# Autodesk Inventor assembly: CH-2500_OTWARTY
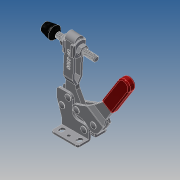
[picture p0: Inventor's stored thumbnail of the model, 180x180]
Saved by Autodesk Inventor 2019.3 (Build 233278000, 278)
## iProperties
Company: Î¢ÈíÖÐ¹ú
Created: 2012-09
Part Number: CH-2500_OTWARTY
Material: Ogólny
Description: STEP AP203
Document SubType Name: Assembly
Designer: CADENGINEERING4
Sending System: SolidWorks 2010
Preprocessor: SwSTEP 2.0
Title: CH-2500.STEP
Author: Î¢ÈíÓÃ»§
Revision Number: ÈÎºÎ
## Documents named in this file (12)
- E:\STRONA\Horizontal toggle clamp\CH-2500\CH-2500_OTWARTY.iam
- E:\STRONA\Horizontal toggle clamp\CH-2500\CH-36092M-06___.ipt
- E:\STRONA\Horizontal toggle clamp\CH-2500\CH-2500-06___.ipt
- E:\STRONA\Horizontal toggle clamp\CH-2500\CH-2500-03___.ipt
- E:\STRONA\Horizontal toggle clamp\CH-2500\CH-FC-56300___.ipt
- E:\STRONA\Horizontal toggle clamp\CH-2500\CH-2500-01___.ipt
- E:\STRONA\Horizontal toggle clamp\CH-2500\CH-11401-05___.ipt
- E:\STRONA\Horizontal toggle clamp\CH-2500\CH-2500-02___.ipt
- E:\STRONA\Horizontal toggle clamp\CH-2500\FW516___.ipt
- E:\STRONA\Horizontal toggle clamp\CH-2500\CH-2500-04___.ipt
- E:\STRONA\Horizontal toggle clamp\CH-2500\CH-FC-56300-02___.ipt
- E:\STRONA\Horizontal toggle clamp\CH-2500\CH-2500-05___.ipt
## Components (20 placed, 20 different names)
1. CH-36092M-06____1 — Zestawiające:24, Równoległe:3, Zestawiające:25
2. CH-2500-06____2 — Zestawiające:33, Zestawiające:34, Zestawiające:35
3. CH-2500-03____3 — Zestawiające:12, Zestawiające:13, Zestawiające:14, Zestawiające:17, Zestawiające:18, Zestawiające:25, Zestawiające:26, Zestawiające:27, Zestawiające:36, Zestawiające:37, Przejściowe:1
4. CH-FC-56300____4 — Równoległe:2, Zestawiające:3, Zestawiające:4, Zestawiające:5, Zestawiające:6, Zestawiające:11
5. CH-2500-01____5 — Zestawiające:15, Zestawiające:16, Zestawiające:19, Zestawiające:20, Zestawiające:21, Zestawiające:22, Zestawiające:28, Zestawiające:29, Zestawiające:30, Zestawiające:31, Zestawiające:32, Zestawiające:34, Zestawiające:35, Przejściowe:1
6. CH-11401-05____6 — Zestawiające:28, Zestawiające:29
7. CH-2500-02____7 — Zestawiające:1, Kątowe:1, Zestawiające:9, Zestawiające:10, Zestawiające:11, Zestawiające:32, Zestawiające:33, Zestawiające:38
8. FW516____8 — Zestawiające:2, Równoległe:1, Zestawiające:6, Zestawiające:7, Zestawiające:10
9. CH-36092M-06____9 — Zestawiające:15, Zestawiające:16
10. CH-2500-04____10 — Zestawiające:21, Zestawiające:22, Zestawiające:23, Zestawiające:24, Równoległe:3, Zestawiające:26
11. CH-2500-06____11 — Zestawiające:30, Zestawiające:31
12. CH-2500-06____12 — Zestawiające:19, Zestawiające:20
13. CH-FC-56300-02____13 — Zestawiające:4, Zestawiające:8
14. CH-2500-06____14 — Zestawiające:36, Zestawiające:37, Zestawiające:38
15. FW516____15 — Równoległe:1, Zestawiające:3, Zestawiające:8, Zestawiające:9
16. CH-36092M-06____16 — Zestawiające:17, Zestawiające:18
17. CH-2500-05____17 — Zestawiające:12, Zestawiające:13, Zestawiające:14
18. CH-FC-56300-02____18 — Równoległe:2, Zestawiające:5, Zestawiające:7
19. CH-2500-06____19 — Zestawiające:23, Zestawiające:27
20. CH-36092M-06____20
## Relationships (43: Mate 38, Flush 3, Angle 1, Transitional 1)
- Zestawiające:1 [Mate]: CH-2500-02____7
- Kątowe:1 [Angle]: CH-2500-02____7
- Zestawiające:2 [Mate]: FW516____8
- Równoległe:1 [Flush]: FW516____8 ↔ FW516____15
- Równoległe:2 [Flush]: CH-FC-56300____4 ↔ CH-FC-56300-02____18
- Zestawiające:3 [Mate]: CH-FC-56300____4 ↔ FW516____15
- Zestawiające:4 [Mate]: CH-FC-56300____4 ↔ CH-FC-56300-02____13
- Zestawiające:5 [Mate]: CH-FC-56300____4 ↔ CH-FC-56300-02____18
- Zestawiające:6 [Mate]: CH-FC-56300____4 ↔ FW516____8
- Zestawiające:7 [Mate]: FW516____8 ↔ CH-FC-56300-02____18
- Zestawiające:8 [Mate]: CH-FC-56300-02____13 ↔ FW516____15
- Zestawiające:9 [Mate]: CH-2500-02____7 ↔ FW516____15
- Zestawiające:10 [Mate]: CH-2500-02____7 ↔ FW516____8
- Zestawiające:11 [Mate]: CH-FC-56300____4 ↔ CH-2500-02____7
- Zestawiające:12 [Mate]: CH-2500-03____3 ↔ CH-2500-05____17
- Zestawiające:13 [Mate]: CH-2500-03____3 ↔ CH-2500-05____17
- Zestawiające:14 [Mate]: CH-2500-03____3 ↔ CH-2500-05____17
- Zestawiające:15 [Mate]: CH-2500-01____5 ↔ CH-36092M-06____9
- Zestawiające:16 [Mate]: CH-2500-01____5 ↔ CH-36092M-06____9
- Zestawiające:17 [Mate]: CH-2500-03____3 ↔ CH-36092M-06____16
- Zestawiające:18 [Mate]: CH-2500-03____3 ↔ CH-36092M-06____16
- Zestawiające:19 [Mate]: CH-2500-01____5 ↔ CH-2500-06____12
- Zestawiające:20 [Mate]: CH-2500-01____5 ↔ CH-2500-06____12
- Zestawiające:21 [Mate]: CH-2500-01____5 ↔ CH-2500-04____10
- Zestawiające:22 [Mate]: CH-2500-01____5 ↔ CH-2500-04____10
- Zestawiające:23 [Mate]: CH-2500-04____10 ↔ CH-2500-06____19
- Zestawiające:24 [Mate]: CH-36092M-06____1 ↔ CH-2500-04____10
- Równoległe:3 [Flush]: CH-36092M-06____1 ↔ CH-2500-04____10
- Zestawiające:25 [Mate]: CH-36092M-06____1 ↔ CH-2500-03____3
- Zestawiające:26 [Mate]: CH-2500-03____3 ↔ CH-2500-04____10
- Zestawiające:27 [Mate]: CH-2500-03____3 ↔ CH-2500-06____19
- Zestawiające:28 [Mate]: CH-2500-01____5 ↔ CH-11401-05____6
- Zestawiające:29 [Mate]: CH-2500-01____5 ↔ CH-11401-05____6
- Zestawiające:30 [Mate]: CH-2500-01____5 ↔ CH-2500-06____11
- Zestawiające:31 [Mate]: CH-2500-01____5 ↔ CH-2500-06____11
- Zestawiające:32 [Mate]: CH-2500-01____5 ↔ CH-2500-02____7
- Zestawiające:33 [Mate]: CH-2500-06____2 ↔ CH-2500-02____7
- Zestawiające:34 [Mate]: CH-2500-06____2 ↔ CH-2500-01____5
- Zestawiające:35 [Mate]: CH-2500-06____2 ↔ CH-2500-01____5
- Zestawiające:36 [Mate]: CH-2500-03____3 ↔ CH-2500-06____14
- Zestawiające:37 [Mate]: CH-2500-03____3 ↔ CH-2500-06____14
- Zestawiające:38 [Mate]: CH-2500-02____7 ↔ CH-2500-06____14
- Przejściowe:1 [Transitional]: CH-2500-03____3 ↔ CH-2500-01____5
